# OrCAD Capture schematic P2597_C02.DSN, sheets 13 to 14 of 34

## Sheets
13 21_GPIO Expanders: size Custom
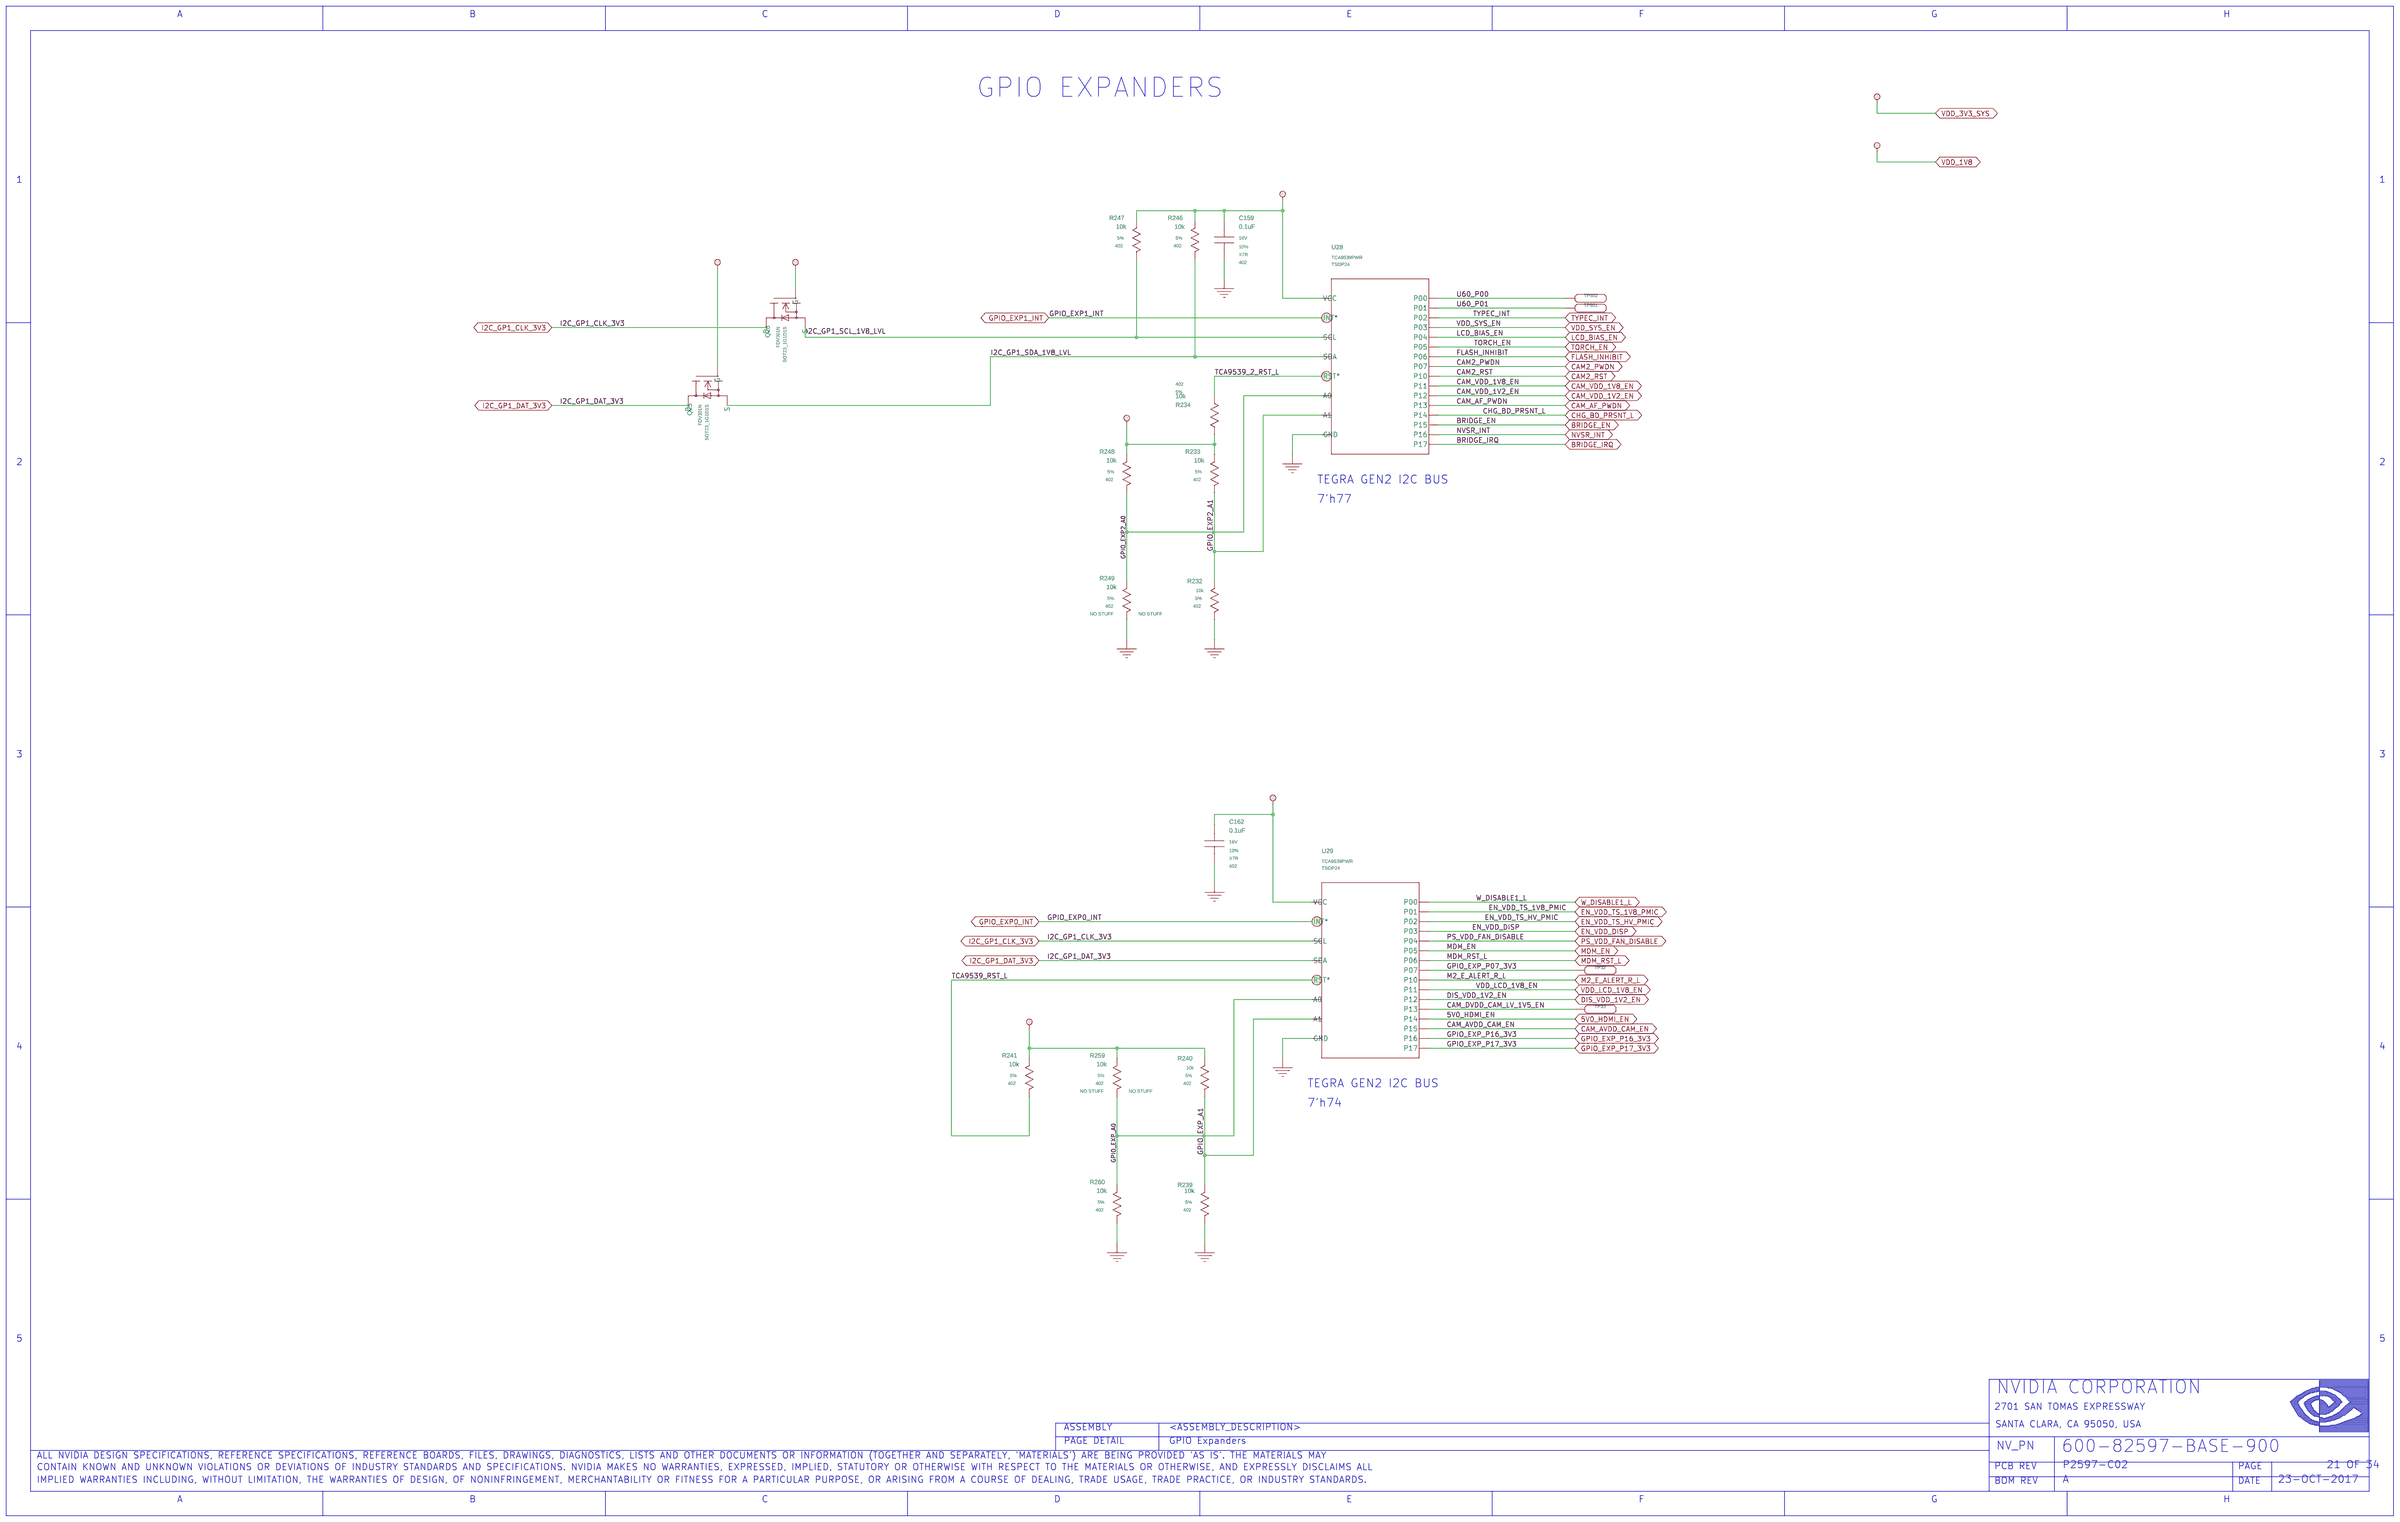
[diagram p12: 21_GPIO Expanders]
14 20_ON OFF CONTROL OUTPUT LOGI: size Custom
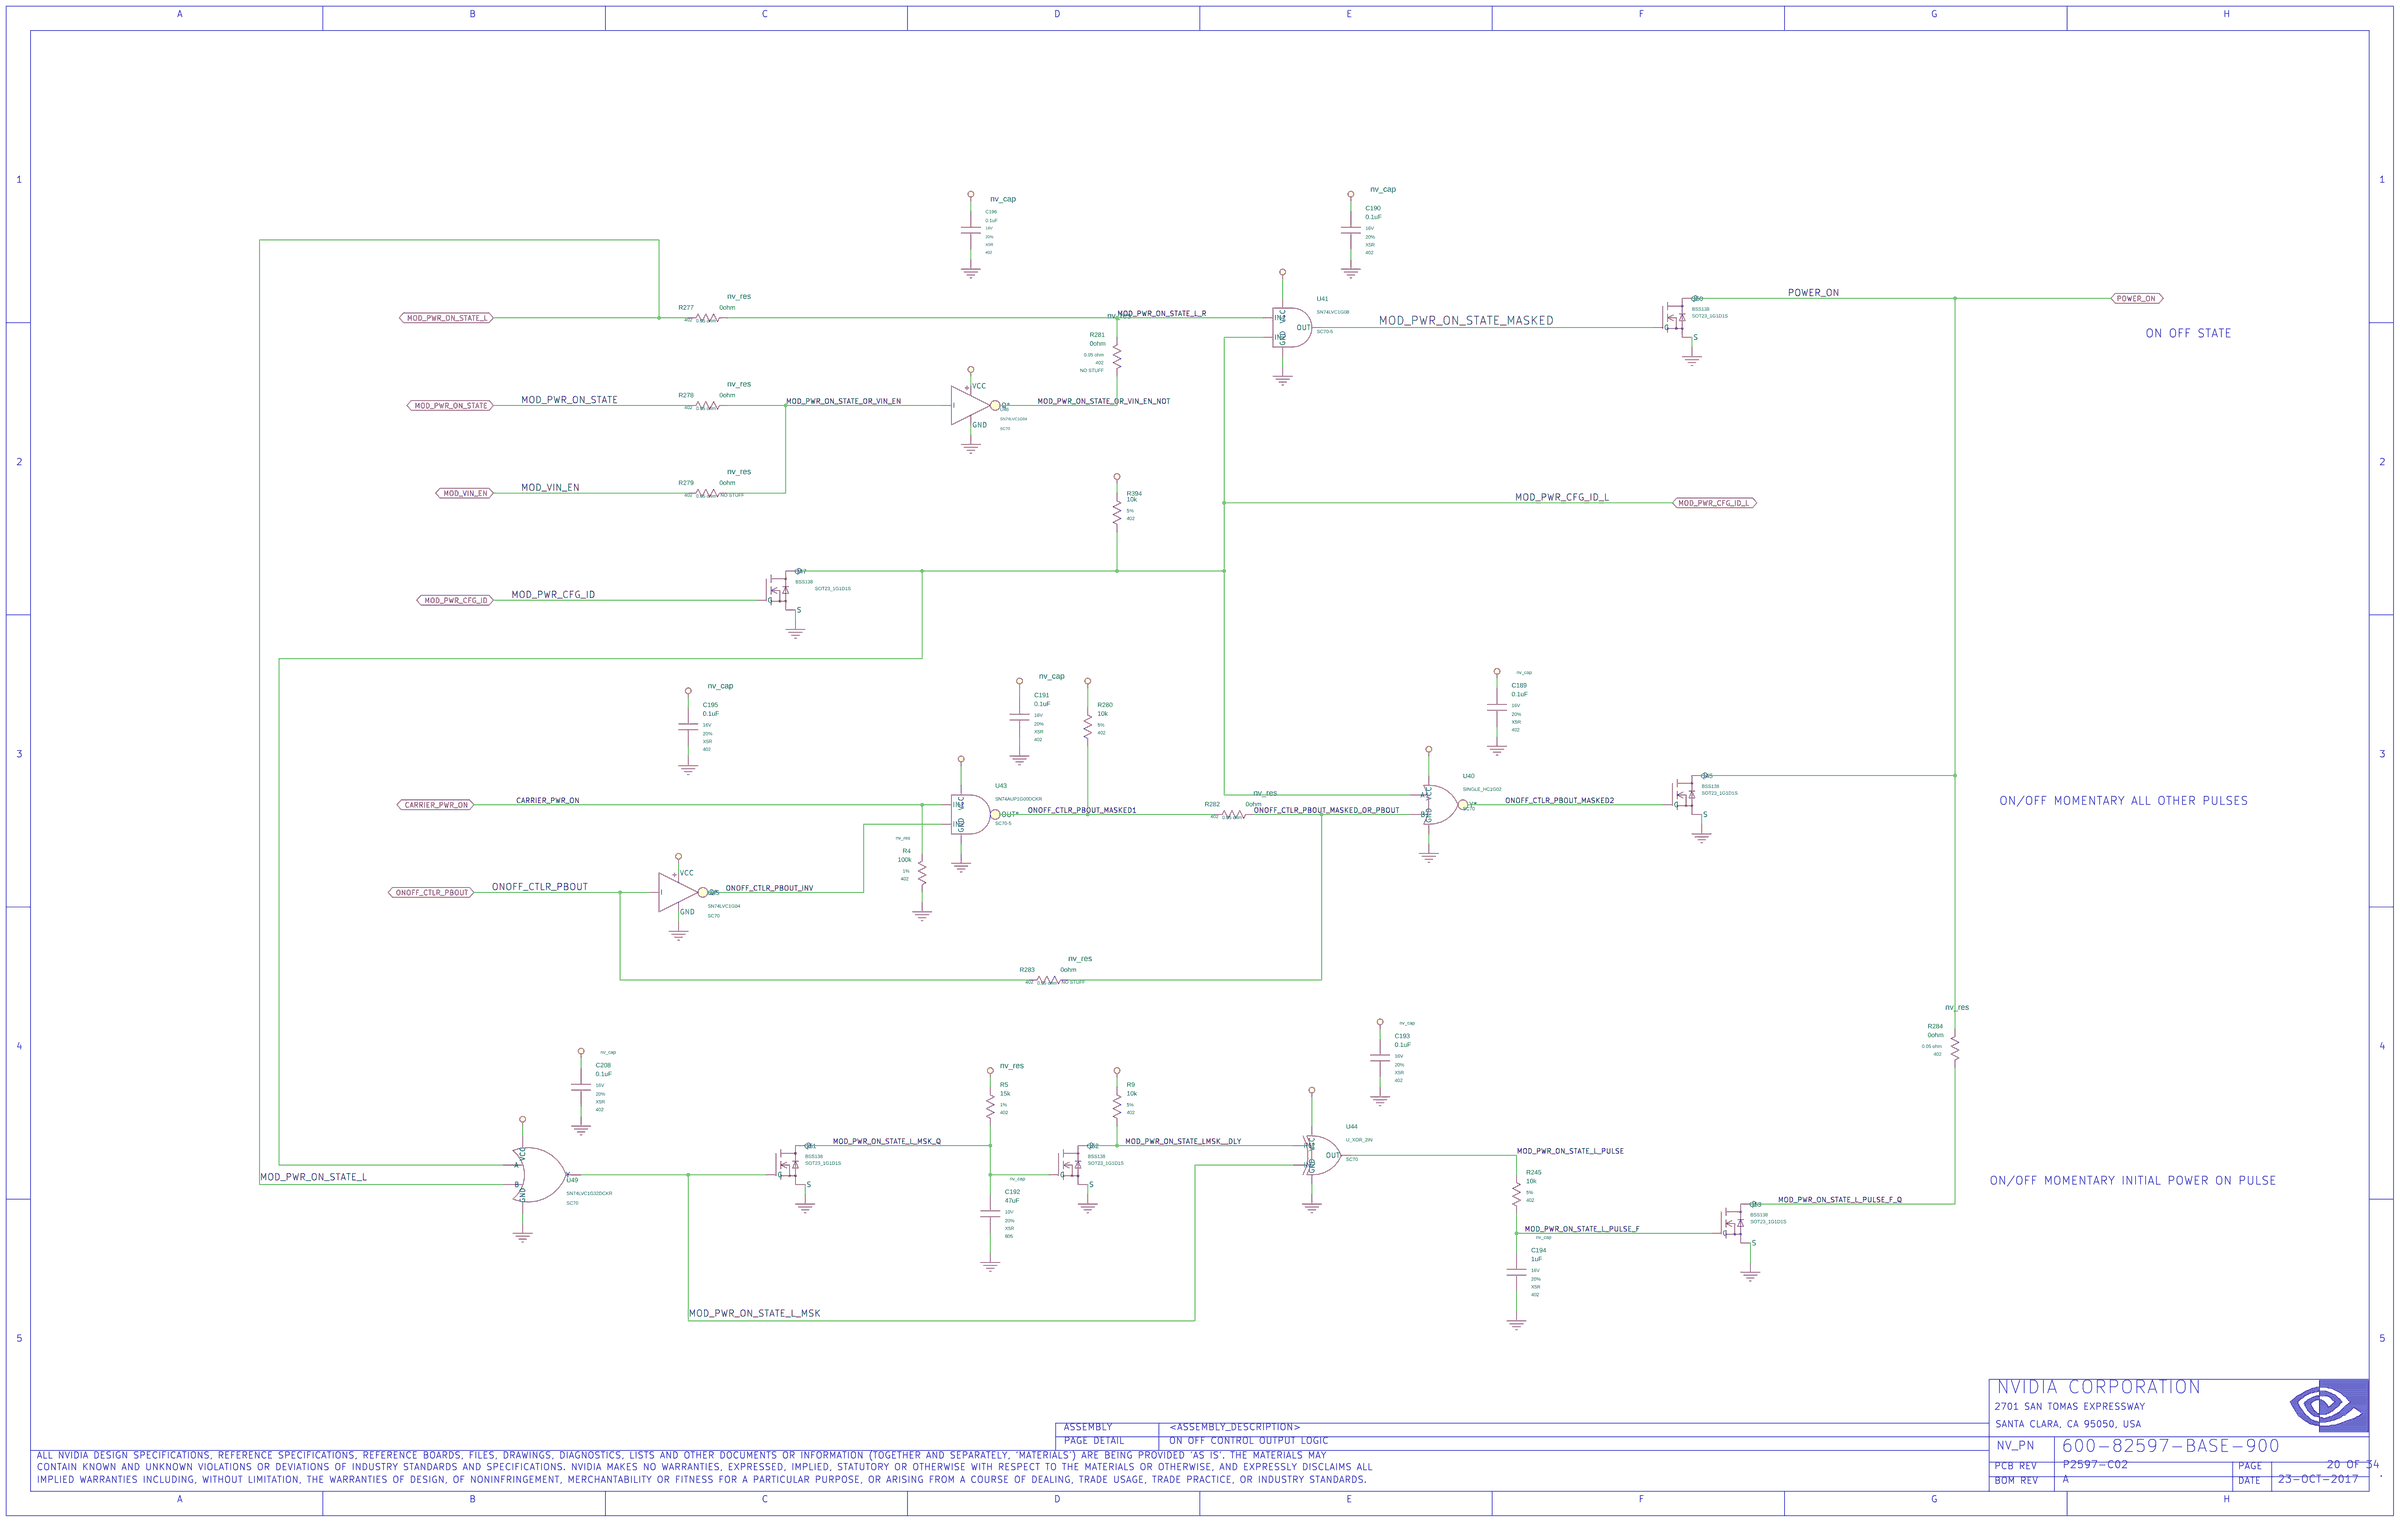
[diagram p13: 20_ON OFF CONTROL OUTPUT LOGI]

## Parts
sheet 20_ON OFF CONTROL OUTPUT LOGI
C189  0.1uF  [402]
C190  0.1uF  [402]
C191  0.1uF  [402]
C192  47uF  [805]
C193  0.1uF  [402]
C194  1uF  [402]
C195  0.1uF  [402]
C196  0.1uF  [402]
C208  0.1uF  [402]
Q45  Q_FET_N_ENH  [SOT23]
Q47  Q_FET_N_ENH  [SOT23]
Q50  Q_FET_N_ENH  [SOT23]
Q51  Q_FET_N_ENH  [SOT23]
Q52  Q_FET_N_ENH  [SOT23]
Q53  Q_FET_N_ENH  [SOT23]
R4  100k  [402]
R5  15k  [402]
R9  10k  [402]
R245  10k  [402]
R277  0ohm  [402]
R278  0ohm  [402]
R279  0ohm  [402]
R280  10k  [402]
R281  0ohm  [402]
R282  0ohm  [402]
R283  0ohm  [402]
R284  0ohm  [402]
R394  10k  [402]
U40  U_NOR_2IN  [SC70_5]
U41  U_AND_2IN  [SC70_5]
U43  U_NAND_2IN  [SC70_5]
U44  U_XOR_2IN  [SC70_5]
U45  U_NOT  [SC70_5]
U46  U_NOT  [SC70_5]
U49  U_OR_2IN  [SC70_5]
sheet 21_GPIO Expanders
C159  0.1uF  [402]
C162  0.1uF  [402]
Q25  Q_FET_N_ENH  [SOT23]
Q26  Q_FET_N_ENH  [SOT23]
R232  10k  [402]
R233  10k  [402]
R234  10k  [402]
R239  10k  [402]
R240  10k  [402]
R241  10k  [402]
R246  10k  [402]
R247  10k  [402]
R248  10k  [402]
R249  10k  [402]
R259  10k  [402]
R260  10k  [402]
TP32  LABTESTPOINT  [LTPT28C49P]
TP33  LABTESTPOINT  [LTPT28C49P]
TP501  LABTESTPOINT  [LTPT28C49P]
TP502  LABTESTPOINT  [LTPT28C49P]
U28  U_I2C_EXP_TCA9539  [XSOP24_P065_079X045]
U29  U_I2C_EXP_TCA9539  [XSOP24_P065_079X045]

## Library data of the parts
C189 = C: ASSEMBLY: ON_OFF_CTRL; CDS_LIB: discrete; CDS_PART_NAME: C_0402-0.1UF,X5R,20%,16V,032-0877-000; CDS_PHYS_PART_NAME: C_0402-0.1UF,X5R,20%,16V,032-0877-000-0.1UF,032-0877-000; CDS_SEC: 1; DEVICE_TYPENAME: C_0402-01UFX5R2016V032-0877-000-01UF032-0877-000; DRAWING: @P2597_C02_LIB.P2597_C02(SCH_1):PAGE20; MAT: X5R; MAX_VOLTAGE: 16V; NV_PN: 032-0877-000; PATH: I11; PHYS_PAGE: 20; ROT: 0; SEC: 1; SIGNAL_MODEL: nv_cap; TOL: 20%; VER: 1; XY: (-4500,4000)
C190 = C: ASSEMBLY: ON_OFF_CTRL; CDS_LIB: discrete; CDS_PART_NAME: C_0402-0.1UF,X5R,20%,16V,032-0877-000; CDS_PHYS_PART_NAME: C_0402-0.1UF,X5R,20%,16V,032-0877-000-0.1UF,032-0877-000; CDS_SEC: 1; DEVICE_TYPENAME: C_0402-01UFX5R2016V032-0877-000-01UF032-0877-000; DRAWING: @P2597_C02_LIB.P2597_C02(SCH_1):PAGE20; MAT: X5R; MAX_VOLTAGE: 16V; NV_PN: 032-0877-000; PATH: I23; PHYS_PAGE: 20; ROT: 0; SEC: 1; SIGNAL_MODEL: nv_cap; TOL: 20%; VER: 1; XY: (-5250,6450)
C191 = C: ASSEMBLY: ON_OFF_CTRL; CDS_LIB: discrete; CDS_PART_NAME: C_0402-0.1UF,X5R,20%,16V,032-0877-000; CDS_PHYS_PART_NAME: C_0402-0.1UF,X5R,20%,16V,032-0877-000-0.1UF,032-0877-000; CDS_SEC: 1; DEVICE_TYPENAME: C_0402-01UFX5R2016V032-0877-000-01UF032-0877-000; DRAWING: @P2597_C02_LIB.P2597_C02(SCH_1):PAGE20; MAT: X5R; MAX_VOLTAGE: 16V; NV_PN: 032-0877-000; PATH: I19; PHYS_PAGE: 20; ROT: 0; SEC: 1; SIGNAL_MODEL: nv_cap; TOL: 20%; VER: 1; XY: (-6950,3950)
C192 = C: ASSEMBLY: ON_OFF_CTRL; CDS_LIB: discrete; CDS_PART_NAME: C_0805-47UF,X5R,20%,10V,032-0775-000; CDS_PHYS_PART_NAME: C_0805-47UF,X5R,20%,10V,032-0775-000-032-0775-000,47UF; CDS_SEC: 1; DEVICE_TYPENAME: C_0805-47UFX5R2010V032-0775-000-032-0775-00047UF; DRAWING: @P2597_C02_LIB.P2597_C02(SCH_1):PAGE20; MAT: X5R; MAX_VOLTAGE: 10V; NV_PN: 032-0775-000; PATH: I42; PHYS_PAGE: 20; ROT: 0; SEC: 1; SIGNAL_MODEL: nv_cap; TOL: 20%; VER: 1; XY: (-7100,1400)
C193 = C: ASSEMBLY: ON_OFF_CTRL; CDS_LIB: discrete; CDS_PART_NAME: C_0402-0.1UF,X5R,20%,16V,032-0877-000; CDS_PHYS_PART_NAME: C_0402-0.1UF,X5R,20%,16V,032-0877-000-0.1UF,032-0877-000; CDS_SEC: 1; DEVICE_TYPENAME: C_0402-01UFX5R2016V032-0877-000-01UF032-0877-000; DRAWING: @P2597_C02_LIB.P2597_C02(SCH_1):PAGE20; MAT: X5R; MAX_VOLTAGE: 16V; NV_PN: 032-0877-000; PATH: I5; PHYS_PAGE: 20; ROT: 0; SEC: 1; SIGNAL_MODEL: nv_cap; TOL: 20%; VER: 1; XY: (-5100,2200)
C194 = C: ASSEMBLY: ON_OFF_CTRL; CDS_LIB: discrete; CDS_PART_NAME: C_0402-1UF,X5R,20%,16V,032-0521-000; CDS_PHYS_PART_NAME: C_0402-1UF,X5R,20%,16V,032-0521-000-032-0521-000,1UF; CDS_SEC: 1; DEVICE_TYPENAME: C_0402-1UFX5R2016V032-0521-000-032-0521-0001UF; DRAWING: @P2597_C02_LIB.P2597_C02(SCH_1):PAGE20; MAT: X5R; MAX_VOLTAGE: 16V; NV_PN: 032-0521-000; PATH: I36; PHYS_PAGE: 20; ROT: 0; SEC: 1; SIGNAL_MODEL: nv_cap; TOL: 20%; VER: 1; XY: (-4400,1100)
C195 = C: ASSEMBLY: ON_OFF_CTRL; CDS_LIB: discrete; CDS_PART_NAME: C_0402-0.1UF,X5R,20%,16V,032-0877-000; CDS_PHYS_PART_NAME: C_0402-0.1UF,X5R,20%,16V,032-0877-000-0.1UF,032-0877-000; CDS_SEC: 1; DEVICE_TYPENAME: C_0402-01UFX5R2016V032-0877-000-01UF032-0877-000; DRAWING: @P2597_C02_LIB.P2597_C02(SCH_1):PAGE20; MAT: X5R; MAX_VOLTAGE: 16V; NV_PN: 032-0877-000; PATH: I55; PHYS_PAGE: 20; ROT: 0; SEC: 1; SIGNAL_MODEL: nv_cap; TOL: 20%; VER: 1; XY: (-8650,3900)
C196 = C: ASSEMBLY: ON_OFF_CTRL; CDS_LIB: discrete; CDS_PART_NAME: C_0402-0.1UF,X5R,20%,16V,032-0877-000; CDS_PHYS_PART_NAME: C_0402-0.1UF,X5R,20%,16V,032-0877-000-0.1UF,032-0877-000; CDS_SEC: 1; DEVICE_TYPENAME: C_0402-01UFX5R2016V032-0877-000-01UF032-0877-000; DRAWING: @P2597_C02_LIB.P2597_C02(SCH_1):PAGE20; MAT: X5R; MAX_VOLTAGE: 16V; NV_PN: 032-0877-000; PATH: I88; PHYS_PAGE: 20; ROT: 0; SEC: 1; SIGNAL_MODEL: nv_cap; TOL: 20%; VER: 1; XY: (-7200,6450)
C208 = C: ASSEMBLY: ON_OFF_CTRL; CDS_LIB: discrete; CDS_PART_NAME: C_0402-0.1UF,X5R,20%,16V,032-0877-000; CDS_PHYS_PART_NAME: C_0402-0.1UF,X5R,20%,16V,032-0877-000-0.1UF,032-0877-000; CDS_SEC: 1; DEVICE_TYPENAME: C_0402-01UFX5R2016V032-0877-000-01UF032-0877-000; DRAWING: @P2597_C02_LIB.P2597_C02(SCH_1):PAGE20; MAT: X5R; MAX_VOLTAGE: 16V; NV_PN: 032-0877-000; PATH: I104; PHYS_PAGE: 20; ROT: 0; SEC: 1; SIGNAL_MODEL: nv_cap; TOL: 20%; VER: 1; XY: (-9200,2050)
Q45 = Q_FET_N_ENH#2: ASSEMBLY: ON_OFF_CTRL; CDS_LIB: discrete; CDS_PART_NAME: Q_FET_N_ENH_SOT23_1G1D1S-BSS138,50V,3500MOHM@10V / 3500MOHM@4.5V / 3500MOHM@2.5V,0.2A,0.2A,20V,0.3W,[ ]@10V / [ ]@4.5V / [ ]@2A; CDS_PHYS_PART_NAME: Q_FET_N_ENH_SOT23_1G1D1S-BSS138,50V,3500MOHM@10V / 3500MOHM@4.5V / 3500MOHM@2.5V,0.2A,0.2A,20V,0.3W,[ ]@10V / [ ]@4.5V / [ ]@2B; CDS_SEC: 1; CONTINUOUS_CURRENT: 0.2A; CaptureCellPackProp: Q_FET_N_ENH__sym_2##2; DEVICE_TYPENAME: Q_FET_N_ENH_SOT23_1G1D1S-BSS13850V3500MOHM10V3500MOHM45V3500MOHM25V02A02A20V03W10V45V2B; DRAWING: @P2597_C02_LIB.P2597_C02(SCH_1):PAGE20; MAX_CURRENT: 0.2A; MAX_VOLTAGE: 50V; MAX_WATTAGE: 0.3W; NV_NAME: BSS138; NV_PN: 300-0156-000; PACK_TYPE: SOT23_1G1D1S; PATH: I9; PHYS_PAGE: 20; Q_G: [ ]@10V / [ ]@4.5V / [ ]@2.5V; ROT: 0; R_DS_ON: 3500mohm@10V / 3500mohm@4.5V / 3500mohm@2.5V; SEC: 1; VER: 2; V_BE_GS: 20V; XY: (-3550,3550)
Q47 = Q_FET_N_ENH#2: ASSEMBLY: ON_OFF_CTRL; CDS_LIB: discrete; CDS_PART_NAME: Q_FET_N_ENH_SOT23_1G1D1S-BSS138,50V,3500MOHM@10V / 3500MOHM@4.5V / 3500MOHM@2.5V,0.2A,0.2A,20V,0.3W,[ ]@10V / [ ]@4.5V / [ ]@2A; CDS_PHYS_PART_NAME: Q_FET_N_ENH_SOT23_1G1D1S-BSS138,50V,3500MOHM@10V / 3500MOHM@4.5V / 3500MOHM@2.5V,0.2A,0.2A,20V,0.3W,[ ]@10V / [ ]@4.5V / [ ]@2B; CDS_SEC: 1; CONTINUOUS_CURRENT: 0.2A; CaptureCellPackProp: Q_FET_N_ENH__sym_2##2; DEVICE_TYPENAME: Q_FET_N_ENH_SOT23_1G1D1S-BSS13850V3500MOHM10V3500MOHM45V3500MOHM25V02A02A20V03W10V45V2B; DRAWING: @P2597_C02_LIB.P2597_C02(SCH_1):PAGE20; MAX_CURRENT: 0.2A; MAX_VOLTAGE: 50V; MAX_WATTAGE: 0.3W; NV_NAME: BSS138; NV_PN: 300-0156-000; PACK_TYPE: SOT23_1G1D1S; PATH: I97; PHYS_PAGE: 20; Q_G: [ ]@10V / [ ]@4.5V / [ ]@2.5V; ROT: 0; R_DS_ON: 3500mohm@10V / 3500mohm@4.5V / 3500mohm@2.5V; SEC: 1; VER: 2; V_BE_GS: 20V; XY: (-8200,4600)
Q50 = Q_FET_N_ENH#2: ASSEMBLY: ON_OFF_CTRL; CDS_LIB: discrete; CDS_PART_NAME: Q_FET_N_ENH_SOT23_1G1D1S-BSS138,50V,3500MOHM@10V / 3500MOHM@4.5V / 3500MOHM@2.5V,0.2A,0.2A,20V,0.3W,[ ]@10V / [ ]@4.5V / [ ]@2A; CDS_PHYS_PART_NAME: Q_FET_N_ENH_SOT23_1G1D1S-BSS138,50V,3500MOHM@10V / 3500MOHM@4.5V / 3500MOHM@2.5V,0.2A,0.2A,20V,0.3W,[ ]@10V / [ ]@4.5V / [ ]@2B; CDS_SEC: 1; CONTINUOUS_CURRENT: 0.2A; CaptureCellPackProp: Q_FET_N_ENH__sym_2##2; DEVICE_TYPENAME: Q_FET_N_ENH_SOT23_1G1D1S-BSS13850V3500MOHM10V3500MOHM45V3500MOHM25V02A02A20V03W10V45V2B; DRAWING: @P2597_C02_LIB.P2597_C02(SCH_1):PAGE20; MAX_CURRENT: 0.2A; MAX_VOLTAGE: 50V; MAX_WATTAGE: 0.3W; NV_NAME: BSS138; NV_PN: 300-0156-000; PACK_TYPE: SOT23_1G1D1S; PATH: I21; PHYS_PAGE: 20; Q_G: [ ]@10V / [ ]@4.5V / [ ]@2.5V; ROT: 0; R_DS_ON: 3500mohm@10V / 3500mohm@4.5V / 3500mohm@2.5V; SEC: 1; VER: 2; V_BE_GS: 20V; XY: (-3600,6000)
Q51 = Q_FET_N_ENH#2: ASSEMBLY: ON_OFF_CTRL; CDS_LIB: discrete; CDS_PART_NAME: Q_FET_N_ENH_SOT23_1G1D1S-BSS138,50V,3500MOHM@10V / 3500MOHM@4.5V / 3500MOHM@2.5V,0.2A,0.2A,20V,0.3W,[ ]@10V / [ ]@4.5V / [ ]@2A; CDS_PHYS_PART_NAME: Q_FET_N_ENH_SOT23_1G1D1S-BSS138,50V,3500MOHM@10V / 3500MOHM@4.5V / 3500MOHM@2.5V,0.2A,0.2A,20V,0.3W,[ ]@10V / [ ]@4.5V / [ ]@2B; CDS_SEC: 1; CONTINUOUS_CURRENT: 0.2A; CaptureCellPackProp: Q_FET_N_ENH__sym_2##2; DEVICE_TYPENAME: Q_FET_N_ENH_SOT23_1G1D1S-BSS13850V3500MOHM10V3500MOHM45V3500MOHM25V02A02A20V03W10V45V2B; DRAWING: @P2597_C02_LIB.P2597_C02(SCH_1):PAGE20; MAX_CURRENT: 0.2A; MAX_VOLTAGE: 50V; MAX_WATTAGE: 0.3W; NV_NAME: BSS138; NV_PN: 300-0156-000; PACK_TYPE: SOT23_1G1D1S; PATH: I46; PHYS_PAGE: 20; Q_G: [ ]@10V / [ ]@4.5V / [ ]@2.5V; ROT: 0; R_DS_ON: 3500mohm@10V / 3500mohm@4.5V / 3500mohm@2.5V; SEC: 1; VER: 2; V_BE_GS: 20V; XY: (-8150,1650)
Q52 = Q_FET_N_ENH#2: ASSEMBLY: ON_OFF_CTRL; CDS_LIB: discrete; CDS_PART_NAME: Q_FET_N_ENH_SOT23_1G1D1S-BSS138,50V,3500MOHM@10V / 3500MOHM@4.5V / 3500MOHM@2.5V,0.2A,0.2A,20V,0.3W,[ ]@10V / [ ]@4.5V / [ ]@2A; CDS_PHYS_PART_NAME: Q_FET_N_ENH_SOT23_1G1D1S-BSS138,50V,3500MOHM@10V / 3500MOHM@4.5V / 3500MOHM@2.5V,0.2A,0.2A,20V,0.3W,[ ]@10V / [ ]@4.5V / [ ]@2B; CDS_SEC: 1; CONTINUOUS_CURRENT: 0.2A; CaptureCellPackProp: Q_FET_N_ENH__sym_2##2; DEVICE_TYPENAME: Q_FET_N_ENH_SOT23_1G1D1S-BSS13850V3500MOHM10V3500MOHM45V3500MOHM25V02A02A20V03W10V45V2B; DRAWING: @P2597_C02_LIB.P2597_C02(SCH_1):PAGE20; MAX_CURRENT: 0.2A; MAX_VOLTAGE: 50V; MAX_WATTAGE: 0.3W; NV_NAME: BSS138; NV_PN: 300-0156-000; PACK_TYPE: SOT23_1G1D1S; PATH: I41; PHYS_PAGE: 20; Q_G: [ ]@10V / [ ]@4.5V / [ ]@2.5V; ROT: 0; R_DS_ON: 3500mohm@10V / 3500mohm@4.5V / 3500mohm@2.5V; SEC: 1; VER: 2; V_BE_GS: 20V; XY: (-6700,1650)
Q53 = Q_FET_N_ENH#2: ASSEMBLY: ON_OFF_CTRL; CDS_LIB: discrete; CDS_PART_NAME: Q_FET_N_ENH_SOT23_1G1D1S-BSS138,50V,3500MOHM@10V / 3500MOHM@4.5V / 3500MOHM@2.5V,0.2A,0.2A,20V,0.3W,[ ]@10V / [ ]@4.5V / [ ]@2A; CDS_PHYS_PART_NAME: Q_FET_N_ENH_SOT23_1G1D1S-BSS138,50V,3500MOHM@10V / 3500MOHM@4.5V / 3500MOHM@2.5V,0.2A,0.2A,20V,0.3W,[ ]@10V / [ ]@4.5V / [ ]@2B; CDS_SEC: 1; CONTINUOUS_CURRENT: 0.2A; CaptureCellPackProp: Q_FET_N_ENH__sym_2##2; DEVICE_TYPENAME: Q_FET_N_ENH_SOT23_1G1D1S-BSS13850V3500MOHM10V3500MOHM45V3500MOHM25V02A02A20V03W10V45V2B; DRAWING: @P2597_C02_LIB.P2597_C02(SCH_1):PAGE20; MAX_CURRENT: 0.2A; MAX_VOLTAGE: 50V; MAX_WATTAGE: 0.3W; NV_NAME: BSS138; NV_PN: 300-0156-000; PACK_TYPE: SOT23_1G1D1S; PATH: I33; PHYS_PAGE: 20; Q_G: [ ]@10V / [ ]@4.5V / [ ]@2.5V; ROT: 0; R_DS_ON: 3500mohm@10V / 3500mohm@4.5V / 3500mohm@2.5V; SEC: 1; VER: 2; V_BE_GS: 20V; XY: (-3300,1350)
R4 = R#1: ASSEMBLY: ON_OFF_CTRL; CDS_LIB: discrete; CDS_PART_NAME: R_0402-100K,1 %,62.5MW,195-0005-000; CDS_PHYS_PART_NAME: R_0402-100K,1 %,62.5MW,195-0005-000-100K,195-0005-000; CDS_SEC: 1; CHIPS_PART_NAME: R; DEVICE_TYPENAME: R_0402-100K1625MW195-0005-000-100K195-0005-000; DRAWING: @P2597_C02_LIB.P2597_C02(SCH_1):PAGE20; MAX_WATTAGE: 62.5mW; NV_PN: 195-0005-000; PATH: I60; PHYS_PAGE: 20; ROT: 2; SEC: 1; SIGNAL_MODEL: nv_res; TOL: 1%; VER: 2; XY: (-7450,3150)
R5 = R#1: ASSEMBLY: ON_OFF_CTRL; CDS_LIB: discrete; CDS_PART_NAME: R_0402-15K,1 %,62.5MW,195-0090-000; CDS_PHYS_PART_NAME: R_0402-15K,1 %,62.5MW,195-0090-000-15K,195-0090-000; CDS_SEC: 1; CHIPS_PART_NAME: R; DEVICE_TYPENAME: R_0402-15K1625MW195-0090-000-15K195-0090-000; DRAWING: @P2597_C02_LIB.P2597_C02(SCH_1):PAGE20; MAX_WATTAGE: 62.5mW; NV_PN: 195-0090-000; PATH: I32; PHYS_PAGE: 20; ROT: 0; SEC: 1; SIGNAL_MODEL: nv_res; TOL: 1%; VER: 2; XY: (-7100,1950)
R9 = R#1: ASSEMBLY: ON_OFF_CTRL; CDS_LIB: discrete; CDS_PART_NAME: R_0402-10K,5 %,62.5MW,195-0486-000; CDS_PHYS_PART_NAME: R_0402-10K,5 %,62.5MW,195-0486-000-10K,195-0486-000; CDS_SEC: 1; CHIPS_PART_NAME: R; DEVICE_TYPENAME: R_0402-10K5625MW195-0486-000-10K195-0486-000; DRAWING: @P2597_C02_LIB.P2597_C02(SCH_1):PAGE20; MAX_WATTAGE: 62.5mW; NV_PN: 195-0486-000; PATH: I29; PHYS_PAGE: 20; ROT: 0; SEC: 1; SIGNAL_MODEL: DEFAULT_RESISTOR_10000OHM_2_1; TOL: 5%; VER: 2; XY: (-6450,1950)
R245 = R#1: ASSEMBLY: ON_OFF_CTRL; CDS_LIB: discrete; CDS_PART_NAME: R_0402-10K,5 %,62.5MW,195-0486-000; CDS_PHYS_PART_NAME: R_0402-10K,5 %,62.5MW,195-0486-000-10K,195-0486-000; CDS_SEC: 1; CHIPS_PART_NAME: R; DEVICE_TYPENAME: R_0402-10K5625MW195-0486-000-10K195-0486-000; DRAWING: @P2597_C02_LIB.P2597_C02(SCH_1):PAGE20; MAX_WATTAGE: 62.5mW; NV_PN: 195-0486-000; PATH: I35; PHYS_PAGE: 20; ROT: 0; SEC: 1; SIGNAL_MODEL: DEFAULT_RESISTOR_10000OHM_2_1; TOL: 5%; VER: 2; XY: (-4400,1500)
R277 = R: ASSEMBLY: ON_OFF_CTRL_STATE_PWRON_INV_BYPASS_CMPLX; CDS_LIB: discrete; CDS_PART_NAME: R_0402-0OHM,0.05 OHM,62.5MW,195-2655-000; CDS_PHYS_PART_NAME: R_0402-0OHM,0.05 OHM,62.5MW,195-2655-000-0OHM,195-2655-000; CDS_SEC: 1; DEVICE_TYPENAME: R_0402-0OHM005OHM625MW195-2655-000-0OHM195-2655-000; DRAWING: @P2597_C02_LIB.P2597_C02(SCH_1):PAGE20; MAX_WATTAGE: 62.5mW; NV_PN: 195-2655-000; PATH: I93; PHYS_PAGE: 20; ROT: 0; SEC: 1; SIGNAL_MODEL: nv_res; TOL: 0.05 ohm; VER: 1; XY: (-8550,6000)
R278 = R: ASSEMBLY: ON_OFF_CTRL_STATE_PWRON2INV_CMPLX; CDS_LIB: discrete; CDS_PART_NAME: R_0402-0OHM,0.05 OHM,62.5MW,195-2655-000; CDS_PHYS_PART_NAME: R_0402-0OHM,0.05 OHM,62.5MW,195-2655-000-0OHM,195-2655-000; CDS_SEC: 1; DEVICE_TYPENAME: R_0402-0OHM005OHM625MW195-2655-000-0OHM195-2655-000; DRAWING: @P2597_C02_LIB.P2597_C02(SCH_1):PAGE20; MAX_WATTAGE: 62.5mW; NV_PN: 195-2655-000; PATH: I92; PHYS_PAGE: 20; ROT: 0; SEC: 1; SIGNAL_MODEL: nv_res; TOL: 0.05 ohm; VER: 1; XY: (-8550,5550)
R279 = R: ASSEMBLY: ON_OFF_CTRL_STATE_VINEN2INV_SMPL; CDS_LIB: discrete; CDS_PART_NAME: R_0402-0OHM,0.05 OHM,62.5MW,195-2655-000; CDS_PHYS_PART_NAME: R_0402-0OHM,0.05 OHM,62.5MW,195-2655-000-0OHM,195-2655-000; CDS_SEC: 1; DEVICE_TYPENAME: R_0402-0OHM005OHM625MW195-2655-000-0OHM195-2655-000; DRAWING: @P2597_C02_LIB.P2597_C02(SCH_1):PAGE20; MAX_WATTAGE: 62.5mW; NV_PN: 195-2655-000; PATH: I91; PHYS_PAGE: 20; ROT: 0; SEC: 1; SIGNAL_MODEL: nv_res; SKU: NO STUFF; TOL: 0.05 ohm; VER: 1; XY: (-8550,5100)
R280 = R#1: ASSEMBLY: ON_OFF_CTRL; CDS_LIB: discrete; CDS_PART_NAME: R_0402-10K,5 %,62.5MW,195-0486-000; CDS_PHYS_PART_NAME: R_0402-10K,5 %,62.5MW,195-0486-000-10K,195-0486-000; CDS_SEC: 1; CHIPS_PART_NAME: R; DEVICE_TYPENAME: R_0402-10K5625MW195-0486-000-10K195-0486-000; DRAWING: @P2597_C02_LIB.P2597_C02(SCH_1):PAGE20; MAX_WATTAGE: 62.5mW; NV_PN: 195-0486-000; PATH: I17; PHYS_PAGE: 20; ROT: 0; SEC: 1; SIGNAL_MODEL: DEFAULT_RESISTOR_10000OHM_2_1; TOL: 5%; VER: 2; XY: (-6600,3900)
R281 = R#1: ASSEMBLY: ON_OFF_CTRL_STATE_PWRON_VIN_INV; CDS_LIB: discrete; CDS_PART_NAME: R_0402-0OHM,0.05 OHM,62.5MW,195-2655-000; CDS_PHYS_PART_NAME: R_0402-0OHM,0.05 OHM,62.5MW,195-2655-000-0OHM,195-2655-000; CDS_SEC: 1; CHIPS_PART_NAME: R; DEVICE_TYPENAME: R_0402-0OHM005OHM625MW195-2655-000-0OHM195-2655-000; DRAWING: @P2597_C02_LIB.P2597_C02(SCH_1):PAGE20; MAX_WATTAGE: 62.5mW; NV_PN: 195-2655-000; PATH: I64; PHYS_PAGE: 20; ROT: 2; SEC: 1; SIGNAL_MODEL: nv_res; SKU: NO STUFF; TOL: 0.05 ohm; VER: 2; XY: (-6450,5800)
R282 = R: ASSEMBLY: ON_OFF_CTRL_MOM_PBOUT_CMPLX; CDS_LIB: discrete; CDS_PART_NAME: R_0402-0OHM,0.05 OHM,62.5MW,195-2655-000; CDS_PHYS_PART_NAME: R_0402-0OHM,0.05 OHM,62.5MW,195-2655-000-0OHM,195-2655-000; CDS_SEC: 1; DEVICE_TYPENAME: R_0402-0OHM005OHM625MW195-2655-000-0OHM195-2655-000; DRAWING: @P2597_C02_LIB.P2597_C02(SCH_1):PAGE20; MAX_WATTAGE: 62.5mW; NV_PN: 195-2655-000; PATH: I15; PHYS_PAGE: 20; ROT: 0; SEC: 1; SIGNAL_MODEL: nv_res; TOL: 0.05 ohm; VER: 1; XY: (-5850,3450)
R283 = R: ASSEMBLY: ON_OFF_CTRL_MOM_PBOUT_SMPL; CDS_LIB: discrete; CDS_PART_NAME: R_0402-0OHM,0.05 OHM,62.5MW,195-2655-000; CDS_PHYS_PART_NAME: R_0402-0OHM,0.05 OHM,62.5MW,195-2655-000-0OHM,195-2655-000; CDS_SEC: 1; DEVICE_TYPENAME: R_0402-0OHM005OHM625MW195-2655-000-0OHM195-2655-000; DRAWING: @P2597_C02_LIB.P2597_C02(SCH_1):PAGE20; MAX_WATTAGE: 62.5mW; NV_PN: 195-2655-000; PATH: I94; PHYS_PAGE: 20; ROT: 0; SEC: 1; SIGNAL_MODEL: nv_res; SKU: NO STUFF; TOL: 0.05 ohm; VER: 1; XY: (-6800,2600)
R284 = R#1: ASSEMBLY: ON_OFF_CTRL_MOM_INIT_PULSE_OUTPUT_CMPLX; CDS_LIB: discrete; CDS_PART_NAME: R_0402-0OHM,0.05 OHM,62.5MW,195-2655-000; CDS_PHYS_PART_NAME: R_0402-0OHM,0.05 OHM,62.5MW,195-2655-000-0OHM,195-2655-000; CDS_SEC: 1; CHIPS_PART_NAME: R; DEVICE_TYPENAME: R_0402-0OHM005OHM625MW195-2655-000-0OHM195-2655-000; DRAWING: @P2597_C02_LIB.P2597_C02(SCH_1):PAGE20; MAX_WATTAGE: 62.5mW; NV_PN: 195-2655-000; PATH: I2; PHYS_PAGE: 20; ROT: 2; SEC: 1; SIGNAL_MODEL: nv_res; TOL: 0.05 ohm; VER: 2; XY: (-2150,2250)
R394 = R#1: ASSEMBLY: ON_OFF_CTRL; CDS_LIB: discrete; CDS_PART_NAME: R_0402-10K,5 %,62.5MW,195-0486-000; CDS_PHYS_PART_NAME: R_0402-10K,5 %,62.5MW,195-0486-000-10K,195-0486-000; CDS_SEC: 1; CHIPS_PART_NAME: R; DEVICE_TYPENAME: R_0402-10K5625MW195-0486-000-10K195-0486-000; DRAWING: @P2597_C02_LIB.P2597_C02(SCH_1):PAGE20; MAX_WATTAGE: 62.5mW; NV_PN: 195-0486-000; PATH: I96; PHYS_PAGE: 20; ROT: 0; SEC: 1; SIGNAL_MODEL: DEFAULT_RESISTOR_10000OHM_2_1; TOL: 5%; VER: 2; XY: (-6450,5000)
U40 = U_NOR_2IN: ASSEMBLY: ON_OFF_CTRL; CDS_LIB: logic; CDS_PART_NAME: U_NOR_2IN_SC70-SINGLE_HC1G02,GATES - NOR - 2 INPUT,115-0919-000; CDS_PHYS_PART_NAME: U_NOR_2IN_SC70-SINGLE_HC1G02,GATES - NOR - 2 INPUT,115-0919-000-115-0919-000; CDS_SEC: 1; DEVICE_TYPENAME: U_NOR_2IN_SC70-SINGLE_HC1G02GATES-NOR-2INPUT115-0919-000-115-0919-000; DRAWING: @P2597_C02_LIB.P2597_C02(SCH_1):PAGE20; FUNCTION: Gates - NOR - 2 input; NV_NAME: SINGLE_HC1G02; NV_PN: 115-0919-000; PACK_TYPE: SC70; PATH: I14; PHYS_PAGE: 20; ROT: 0; SEC: 1; VER: 1; XY: (-4800,3500)
U41 = U_AND_2IN: ASSEMBLY: ON_OFF_CTRL; CDS_LIB: logic; CDS_PART_NAME: U_AND_2IN_SC70-5-SN74LVC1G08,GATES - AND - 2 INPUT,115-0014-000; CDS_PHYS_PART_NAME: U_AND_2IN_SC70-5-SN74LVC1G08,GATES - AND - 2 INPUT,115-0014-000-115-0014-000; CDS_SEC: 1; DEVICE_TYPENAME: U_AND_2IN_SC70-5-SN74LVC1G08GATES-AND-2INPUT115-0014-000-115-0014-000; DRAWING: @P2597_C02_LIB.P2597_C02(SCH_1):PAGE20; FUNCTION: Gates - AND - 2 input; NV_NAME: SN74LVC1G08; NV_PN: 115-0014-000; PACK_TYPE: SC70-5; PATH: I30; PHYS_PAGE: 20; ROT: 0; SEC: 1; VER: 1; XY: (-5550,5950)
U43 = U_NAND_2IN: ASSEMBLY: ON_OFF_CTRL; CDS_LIB: logic; CDS_PART_NAME: U_NAND_2IN_SC70-5-SN74AUP1G00DCKR,GATES - NAND - 2 INPUT,115-2151-000; CDS_PHYS_PART_NAME: U_NAND_2IN_SC70-5-SN74AUP1G00DCKR,GATES - NAND - 2 INPUT,115-2151-000-115-2151-000; CDS_SEC: 1; DEVICE_TYPENAME: U_NAND_2IN_SC70-5-SN74AUP1G00DCKRGATES-NAND-2INPUT115-2151-000-115-2151-000; DRAWING: @P2597_C02_LIB.P2597_C02(SCH_1):PAGE20; FUNCTION: Gates - NAND - 2 input; NV_NAME: SN74AUP1G00DCKR; NV_PN: 115-2151-000; PACK_TYPE: SC70-5; PATH: I53; PHYS_PAGE: 20; ROT: 0; SEC: 1; VER: 1; XY: (-7200,3450)
U44 = U_XOR_2IN: ASSEMBLY: ON_OFF_CTRL; CDS_LIB: logic; CDS_PART_NAME: U_XOR_2IN_SC70-U_XOR_2IN,GATES - XOR - 2 INPUT,115-0406-000; CDS_PHYS_PART_NAME: U_XOR_2IN_SC70-U_XOR_2IN,GATES - XOR - 2 INPUT,115-0406-000-115-0406-000; CDS_SEC: 1; DEVICE_TYPENAME: U_XOR_2IN_SC70-U_XOR_2INGATES-XOR-2INPUT115-0406-000-115-0406-000; DRAWING: @P2597_C02_LIB.P2597_C02(SCH_1):PAGE20; FUNCTION: Gates - XOR - 2 input; NV_PN: 115-0406-000; PACK_TYPE: SC70; PATH: I38; PHYS_PAGE: 20; ROT: 0; SEC: 1; VER: 1; XY: (-5400,1700)
U45 = U_NOT: ASSEMBLY: ON_OFF_CTRL; CDS_LIB: logic; CDS_PART_NAME: U_NOT_SC70-SN74LVC1G04,GATES - NOT,115-0085-000; CDS_PHYS_PART_NAME: U_NOT_SC70-SN74LVC1G04,GATES - NOT,115-0085-000-115-0085-000; CDS_SEC: 1; DEVICE_TYPENAME: U_NOT_SC70-SN74LVC1G04GATES-NOT115-0085-000-115-0085-000; DRAWING: @P2597_C02_LIB.P2597_C02(SCH_1):PAGE20; FUNCTION: Gates - NOT; NV_NAME: SN74LVC1G04; NV_PN: 115-0085-000; PACK_TYPE: SC70; PATH: I66; PHYS_PAGE: 20; ROT: 0; SEC: 1; VER: 1; XY: (-8700,3050)
U46 = U_NOT: ASSEMBLY: ON_OFF_CTRL; CDS_LIB: logic; CDS_PART_NAME: U_NOT_SC70-SN74LVC1G04,GATES - NOT,115-0085-000; CDS_PHYS_PART_NAME: U_NOT_SC70-SN74LVC1G04,GATES - NOT,115-0085-000-115-0085-000; CDS_SEC: 1; DEVICE_TYPENAME: U_NOT_SC70-SN74LVC1G04GATES-NOT115-0085-000-115-0085-000; DRAWING: @P2597_C02_LIB.P2597_C02(SCH_1):PAGE20; FUNCTION: Gates - NOT; NV_NAME: SN74LVC1G04; NV_PN: 115-0085-000; PACK_TYPE: SC70; PATH: I83; PHYS_PAGE: 20; ROT: 0; SEC: 1; VER: 1; XY: (-7200,5550)
U49 = U_OR_2IN: ASSEMBLY: ON_OFF_CTRL; CDS_LIB: logic; CDS_PART_NAME: U_OR_2IN_SC70-SN74LVC1G32DCKR,GATES - OR - 2 INPUT,115-1426-000; CDS_PHYS_PART_NAME: U_OR_2IN_SC70-SN74LVC1G32DCKR,GATES - OR - 2 INPUT,115-1426-000-115-1426-000; CDS_SEC: 1; DEVICE_TYPENAME: U_OR_2IN_SC70-SN74LVC1G32DCKRGATES-OR-2INPUT115-1426-000-115-1426-000; DRAWING: @P2597_C02_LIB.P2597_C02(SCH_1):PAGE20; FUNCTION: Gates - OR - 2 input; NV_NAME: SN74LVC1G32DCKR; NV_PN: 115-1426-000; PACK_TYPE: SC70; PATH: I100; PHYS_PAGE: 20; ROT: 0; SEC: 1; VER: 1; XY: (-9400,1600)
C159 = C: ASSEMBLY: GPIO; CDS_LIB: discrete; CDS_PART_NAME: C_0402-0.1UF,X7R,10%,16V,036-0014-000; CDS_PHYS_PART_NAME: C_0402-0.1UF,X7R,10%,16V,036-0014-000-0.1UF,036-0014-000; CDS_SEC: 1; DEVICE_TYPENAME: C_0402-01UFX7R1016V036-0014-000-01UF036-0014-000; DRAWING: @P2597_C02_LIB.P2597_C02(SCH_1):PAGE21; MAT: X7R; MAX_VOLTAGE: 16V; NV_PN: 036-0014-000; PATH: I274; PHYS_PAGE: 21; ROT: 0; SEC: 1; SIGNAL_MODEL: nv_cap; TOL: 10%; VER: 1; XY: (-5900,6400)
C162 = C: ASSEMBLY: GPIO; CDS_LIB: discrete; CDS_PART_NAME: C_0402-0.1UF,X7R,10%,16V,036-0014-000; CDS_PHYS_PART_NAME: C_0402-0.1UF,X7R,10%,16V,036-0014-000-0.1UF,036-0014-000; CDS_SEC: 1; DEVICE_TYPENAME: C_0402-01UFX7R1016V036-0014-000-01UF036-0014-000; DRAWING: @P2597_C02_LIB.P2597_C02(SCH_1):PAGE21; MAT: X7R; MAX_VOLTAGE: 16V; NV_PN: 036-0014-000; PATH: I53; PHYS_PAGE: 21; ROT: 0; SEC: 1; SIGNAL_MODEL: nv_cap; TOL: 10%; VER: 1; XY: (-5950,3300)
Q25 = Q_FET_N_ENH#2: ASSEMBLY: GPIO; CDS_LIB: discrete; CDS_PART_NAME: Q_FET_N_ENH_SOT23_1G1D1S-FDV301N,25V,-1000MOHM@10V / 4000MOHM@4.5V / -1000MOHM@2.5V,0.22A,0.5A,8V,0.35W,[ ]@10V / [ ]@4.5V / [A; CDS_PHYS_PART_NAME: Q_FET_N_ENH_SOT23_1G1D1S-FDV301N,25V,-1000MOHM@10V / 4000MOHM@4.5V / -1000MOHM@2.5V,0.22A,0.5A,8V,0.35W,[ ]@10V / [ ]@4.5V / [B; CDS_SEC: 1; CONTINUOUS_CURRENT: 0.22A; CaptureCellPackProp: Q_FET_N_ENH__sym_2##2; DEVICE_TYPENAME: Q_FET_N_ENH_SOT23_1G1D1S-FDV301N25V-1000MOHM10V4000MOHM45V-1000MOHM25V022A05A8V035W10V45VB; DRAWING: @P2597_C02_LIB.P2597_C02(SCH_1):PAGE21; MAX_CURRENT: 0.5A; MAX_VOLTAGE: 25V; MAX_WATTAGE: 0.35W; NV_NAME: FDV301N; NV_PN: 300-0494-000; PACK_TYPE: SOT23_1G1D1S; PATH: I282; PHYS_PAGE: 21; Q_G: [ ]@10V / [ ]@4.5V / [ ]@2.5V; ROT: 3; R_DS_ON: -1000mohm@10V / 4000mohm@4.5V / -1000mohm@2.5V; SEC: 1; SEC_TYPE: SOT23_1G1D1S; VER: 2; V_BE_GS: 8V; XY: (-8550,5650)
Q26 = Q_FET_N_ENH#2: ASSEMBLY: GPIO; CDS_LIB: discrete; CDS_PART_NAME: Q_FET_N_ENH_SOT23_1G1D1S-FDV301N,25V,-1000MOHM@10V / 4000MOHM@4.5V / -1000MOHM@2.5V,0.22A,0.5A,8V,0.35W,[ ]@10V / [ ]@4.5V / [A; CDS_PHYS_PART_NAME: Q_FET_N_ENH_SOT23_1G1D1S-FDV301N,25V,-1000MOHM@10V / 4000MOHM@4.5V / -1000MOHM@2.5V,0.22A,0.5A,8V,0.35W,[ ]@10V / [ ]@4.5V / [B; CDS_SEC: 1; CONTINUOUS_CURRENT: 0.22A; CaptureCellPackProp: Q_FET_N_ENH__sym_2##2; DEVICE_TYPENAME: Q_FET_N_ENH_SOT23_1G1D1S-FDV301N25V-1000MOHM10V4000MOHM45V-1000MOHM25V022A05A8V035W10V45VB; DRAWING: @P2597_C02_LIB.P2597_C02(SCH_1):PAGE21; MAX_CURRENT: 0.5A; MAX_VOLTAGE: 25V; MAX_WATTAGE: 0.35W; NV_NAME: FDV301N; NV_PN: 300-0494-000; PACK_TYPE: SOT23_1G1D1S; PATH: I283; PHYS_PAGE: 21; Q_G: [ ]@10V / [ ]@4.5V / [ ]@2.5V; ROT: 3; R_DS_ON: -1000mohm@10V / 4000mohm@4.5V / -1000mohm@2.5V; SEC: 1; SEC_TYPE: SOT23_1G1D1S; VER: 2; V_BE_GS: 8V; XY: (-8150,6050)
R232 = R#1: ASSEMBLY: GPIO; CDS_LIB: discrete; CDS_PART_NAME: R_0402-10K,5 %,62.5MW,195-0486-000; CDS_PHYS_PART_NAME: R_0402-10K,5 %,62.5MW,195-0486-000-10K,195-0486-000; CDS_SEC: 1; CHIPS_PART_NAME: R; DEVICE_TYPENAME: R_0402-10K5625MW195-0486-000-10K195-0486-000; DRAWING: @P2597_C02_LIB.P2597_C02(SCH_1):PAGE21; MAX_WATTAGE: 62.5mW; NV_PN: 195-0486-000; PATH: I247; PHYS_PAGE: 21; ROT: 2; SEC: 1; SIGNAL_MODEL: nv_res; SKU: NO STUFF; TOL: 5%; VER: 2; XY: (-5950,4550)
R233 = R#1: ASSEMBLY: GPIO; CDS_LIB: discrete; CDS_PART_NAME: R_0402-10K,5 %,62.5MW,195-0486-000; CDS_PHYS_PART_NAME: R_0402-10K,5 %,62.5MW,195-0486-000-10K,195-0486-000; CDS_SEC: 1; CHIPS_PART_NAME: R; DEVICE_TYPENAME: R_0402-10K5625MW195-0486-000-10K195-0486-000; DRAWING: @P2597_C02_LIB.P2597_C02(SCH_1):PAGE21; MAX_WATTAGE: 62.5mW; NV_PN: 195-0486-000; PATH: I253; PHYS_PAGE: 21; ROT: 2; SEC: 1; SIGNAL_MODEL: nv_res; TOL: 5%; VER: 2; XY: (-5950,5200)
R234 = R#1: ASSEMBLY: GPIO; CDS_LIB: discrete; CDS_PART_NAME: R_0402-10K,5 %,62.5MW,195-0486-000; CDS_PHYS_PART_NAME: R_0402-10K,5 %,62.5MW,195-0486-000-10K,195-0486-000; CDS_SEC: 1; CHIPS_PART_NAME: R; DEVICE_TYPENAME: R_0402-10K5625MW195-0486-000-10K195-0486-000; DRAWING: @P2597_C02_LIB.P2597_C02(SCH_1):PAGE21; MAX_WATTAGE: 62.5mW; NV_PN: 195-0486-000; PATH: I256; PHYS_PAGE: 21; ROT: 4; SEC: 1; SIGNAL_MODEL: nv_res; TOL: 5%; VER: 2; XY: (-5950,5500)
R239 = R#1: ASSEMBLY: GPIO; CDS_LIB: discrete; CDS_PART_NAME: R_0402-10K,5 %,62.5MW,195-0486-000; CDS_PHYS_PART_NAME: R_0402-10K,5 %,62.5MW,195-0486-000-10K,195-0486-000; CDS_SEC: 1; CHIPS_PART_NAME: R; DEVICE_TYPENAME: R_0402-10K5625MW195-0486-000-10K195-0486-000; DRAWING: @P2597_C02_LIB.P2597_C02(SCH_1):PAGE21; MAX_WATTAGE: 62.5mW; NV_PN: 195-0486-000; PATH: I30; PHYS_PAGE: 21; ROT: 2; SEC: 1; SIGNAL_MODEL: nv_res; TOL: 5%; VER: 2; XY: (-6000,1450)
R240 = R#1: ASSEMBLY: GPIO; CDS_LIB: discrete; CDS_PART_NAME: R_0402-10K,5 %,62.5MW,195-0486-000; CDS_PHYS_PART_NAME: R_0402-10K,5 %,62.5MW,195-0486-000-10K,195-0486-000; CDS_SEC: 1; CHIPS_PART_NAME: R; DEVICE_TYPENAME: R_0402-10K5625MW195-0486-000-10K195-0486-000; DRAWING: @P2597_C02_LIB.P2597_C02(SCH_1):PAGE21; MAX_WATTAGE: 62.5mW; NV_PN: 195-0486-000; PATH: I32; PHYS_PAGE: 21; ROT: 2; SEC: 1; SIGNAL_MODEL: nv_res; SKU: NO STUFF; TOL: 5%; VER: 2; XY: (-6000,2100)
R241 = R#1: ASSEMBLY: GPIO; CDS_LIB: discrete; CDS_PART_NAME: R_0402-10K,5 %,62.5MW,195-0486-000; CDS_PHYS_PART_NAME: R_0402-10K,5 %,62.5MW,195-0486-000-10K,195-0486-000; CDS_SEC: 1; CHIPS_PART_NAME: R; DEVICE_TYPENAME: R_0402-10K5625MW195-0486-000-10K195-0486-000; DRAWING: @P2597_C02_LIB.P2597_C02(SCH_1):PAGE21; MAX_WATTAGE: 62.5mW; NV_PN: 195-0486-000; PATH: I208; PHYS_PAGE: 21; ROT: 2; SEC: 1; SIGNAL_MODEL: nv_res; TOL: 5%; VER: 2; XY: (-6900,2100)
R246 = R#1: ASSEMBLY: GPIO; CDS_LIB: discrete; CDS_PART_NAME: R_0402-10K,5 %,62.5MW,195-0486-000; CDS_PHYS_PART_NAME: R_0402-10K,5 %,62.5MW,195-0486-000-10K,195-0486-000; CDS_SEC: 1; CHIPS_PART_NAME: R; DEVICE_TYPENAME: R_0402-10K5625MW195-0486-000-10K195-0486-000; DRAWING: @P2597_C02_LIB.P2597_C02(SCH_1):PAGE21; MAX_WATTAGE: 62.5mW; NV_PN: 195-0486-000; PATH: I286; PHYS_PAGE: 21; ROT: 2; SEC: 1; SIGNAL_MODEL: nv_res; TOL: 5%; VER: 2; XY: (-6050,6400)
R247 = R#1: ASSEMBLY: GPIO; CDS_LIB: discrete; CDS_PART_NAME: R_0402-10K,5 %,62.5MW,195-0486-000; CDS_PHYS_PART_NAME: R_0402-10K,5 %,62.5MW,195-0486-000-10K,195-0486-000; CDS_SEC: 1; CHIPS_PART_NAME: R; DEVICE_TYPENAME: R_0402-10K5625MW195-0486-000-10K195-0486-000; DRAWING: @P2597_C02_LIB.P2597_C02(SCH_1):PAGE21; MAX_WATTAGE: 62.5mW; NV_PN: 195-0486-000; PATH: I287; PHYS_PAGE: 21; ROT: 2; SEC: 1; SIGNAL_MODEL: nv_res; TOL: 5%; VER: 2; XY: (-6350,6400)
R248 = R#1: ASSEMBLY: GPIO; CDS_LIB: discrete; CDS_PART_NAME: R_0402-10K,5 %,62.5MW,195-0486-000; CDS_PHYS_PART_NAME: R_0402-10K,5 %,62.5MW,195-0486-000-10K,195-0486-000; CDS_SEC: 1; CHIPS_PART_NAME: R; DEVICE_TYPENAME: R_0402-10K5625MW195-0486-000-10K195-0486-000; DRAWING: @P2597_C02_LIB.P2597_C02(SCH_1):PAGE21; MAX_WATTAGE: 62.5mW; NV_PN: 195-0486-000; PATH: I254; PHYS_PAGE: 21; ROT: 2; SEC: 1; SIGNAL_MODEL: nv_res; TOL: 5%; VER: 2; XY: (-6400,5200)
R249 = R#1: ASSEMBLY: GPIO; CDS_LIB: discrete; CDS_PART_NAME: R_0402-10K,5 %,62.5MW,195-0486-000; CDS_PHYS_PART_NAME: R_0402-10K,5 %,62.5MW,195-0486-000-10K,195-0486-000; CDS_SEC: 1; CHIPS_PART_NAME: R; DEVICE_TYPENAME: R_0402-10K5625MW195-0486-000-10K195-0486-000; DRAWING: @P2597_C02_LIB.P2597_C02(SCH_1):PAGE21; MAX_WATTAGE: 62.5mW; NV_PN: 195-0486-000; PATH: I248; PHYS_PAGE: 21; ROT: 2; SEC: 1; SIGNAL_MODEL: nv_res; SKU: NO STUFF; TOL: 5%; VER: 2; XY: (-6400,4550)
R259 = R#1: ASSEMBLY: GPIO; CDS_LIB: discrete; CDS_PART_NAME: R_0402-10K,5 %,62.5MW,195-0486-000; CDS_PHYS_PART_NAME: R_0402-10K,5 %,62.5MW,195-0486-000-10K,195-0486-000; CDS_SEC: 1; CHIPS_PART_NAME: R; DEVICE_TYPENAME: R_0402-10K5625MW195-0486-000-10K195-0486-000; DRAWING: @P2597_C02_LIB.P2597_C02(SCH_1):PAGE21; MAX_WATTAGE: 62.5mW; NV_PN: 195-0486-000; PATH: I31; PHYS_PAGE: 21; ROT: 2; SEC: 1; SIGNAL_MODEL: nv_res; SKU: NO STUFF; TOL: 5%; VER: 2; XY: (-6450,2100)
R260 = R#1: ASSEMBLY: GPIO; CDS_LIB: discrete; CDS_PART_NAME: R_0402-10K,5 %,62.5MW,195-0486-000; CDS_PHYS_PART_NAME: R_0402-10K,5 %,62.5MW,195-0486-000-10K,195-0486-000; CDS_SEC: 1; CHIPS_PART_NAME: R; DEVICE_TYPENAME: R_0402-10K5625MW195-0486-000-10K195-0486-000; DRAWING: @P2597_C02_LIB.P2597_C02(SCH_1):PAGE21; MAX_WATTAGE: 62.5mW; NV_PN: 195-0486-000; PATH: I26; PHYS_PAGE: 21; ROT: 2; SEC: 1; SIGNAL_MODEL: nv_res; TOL: 5%; VER: 2; XY: (-6450,1450)
TP32 = LABTESTPOINT: CDS_LIB: electro_mechanic; CDS_PART_NAME: LABTESTPOINT_B28-LABTESTPOINT; CDS_PHYS_PART_NAME: LABTESTPOINT_B28-LABTESTPOINT; CDS_SEC: 1; DEVICE_TYPENAME: LABTESTPOINT_B28-LABTESTPOINT; DRAWING: @P2597_C02_LIB.P2597_C02(SCH_1):PAGE21; PACK_TYPE: B28; PATH: I293; PHYS_PAGE: 21; ROT: 0; SEC: 1; VER: 3; XY: (-4050,2650)
TP33 = LABTESTPOINT: CDS_LIB: electro_mechanic; CDS_PART_NAME: LABTESTPOINT_B28-LABTESTPOINT; CDS_PHYS_PART_NAME: LABTESTPOINT_B28-LABTESTPOINT; CDS_SEC: 1; DEVICE_TYPENAME: LABTESTPOINT_B28-LABTESTPOINT; DRAWING: @P2597_C02_LIB.P2597_C02(SCH_1):PAGE21; PACK_TYPE: B28; PATH: I290; PHYS_PAGE: 21; ROT: 0; SEC: 1; VER: 3; XY: (-4050,2450)
TP501 = LABTESTPOINT: CDS_LIB: electro_mechanic; CDS_PART_NAME: LABTESTPOINT_B28-LABTESTPOINT; CDS_PHYS_PART_NAME: LABTESTPOINT_B28-LABTESTPOINT; CDS_SEC: 1; DEVICE_TYPENAME: LABTESTPOINT_B28-LABTESTPOINT; DRAWING: @P2597_C02_LIB.P2597_C02(SCH_1):PAGE21; PACK_TYPE: B28; PATH: I292; PHYS_PAGE: 21; ROT: 0; SEC: 1; VER: 3; XY: (-4100,6050)
TP502 = LABTESTPOINT: CDS_LIB: electro_mechanic; CDS_PART_NAME: LABTESTPOINT_B28-LABTESTPOINT; CDS_PHYS_PART_NAME: LABTESTPOINT_B28-LABTESTPOINT; CDS_SEC: 1; DEVICE_TYPENAME: LABTESTPOINT_B28-LABTESTPOINT; DRAWING: @P2597_C02_LIB.P2597_C02(SCH_1):PAGE21; PACK_TYPE: B28; PATH: I291; PHYS_PAGE: 21; ROT: 0; SEC: 1; VER: 3; XY: (-4100,6100)
U28 = U_I2C_EXP_TCA9539: ASSEMBLY: GPIO; CDS_LIB: digital; CDS_PART_NAME: U_I2C_EXP_TCA9539_TSOP24-TCA9539PWR,I/O EXPANDER,115-0674-000; CDS_PHYS_PART_NAME: U_I2C_EXP_TCA9539_TSOP24-TCA9539PWR,I/O EXPANDER,115-0674-000-115-0674-000; CDS_SEC: 1; DEVICE_TYPENAME: U_I2C_EXP_TCA9539_TSOP24-TCA9539PWRIOEXPANDER115-0674-000-115-0674-000; DRAWING: @P2597_C02_LIB.P2597_C02(SCH_1):PAGE21; INTERFACE: I/O Expander; NV_NAME: TCA9539PWR; NV_PN: 115-0674-000; PACK_TYPE: TSOP24; PATH: I276; PHYS_PAGE: 21; ROT: 0; SEC: 1; SEC_TYPE: TSOP24; VER: 1; XY: (-5100,5750)
U29 = U_I2C_EXP_TCA9539: ASSEMBLY: GPIO; CDS_LIB: digital; CDS_PART_NAME: U_I2C_EXP_TCA9539_TSOP24-TCA9539PWR,I/O EXPANDER,115-0674-000; CDS_PHYS_PART_NAME: U_I2C_EXP_TCA9539_TSOP24-TCA9539PWR,I/O EXPANDER,115-0674-000-115-0674-000; CDS_SEC: 1; DEVICE_TYPENAME: U_I2C_EXP_TCA9539_TSOP24-TCA9539PWRIOEXPANDER115-0674-000-115-0674-000; DRAWING: @P2597_C02_LIB.P2597_C02(SCH_1):PAGE21; INTERFACE: I/O Expander; NV_NAME: TCA9539PWR; NV_PN: 115-0674-000; PACK_TYPE: TSOP24; PATH: I2; PHYS_PAGE: 21; ROT: 0; SEC: 1; SEC_TYPE: TSOP24; VER: 1; XY: (-5150,2650)

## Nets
5V0_AO: C189.1 C190.1 C191.1 C193.1 C195.1 C196.1 C208.1 R5.1 R9.1 R280.1 R394.1 U40.5(VCC) U41.5(VCC) U43.5(VCC) U44.5(VCC) U45.5(VCC) U46.5(VCC) U49.5(VCC) ; also on sheet 7 15
5V0_HDMI_EN: U29.17(P14) ; also on sheet 20
GND: C159.2 C162.2 C189.2 C190.2 C191.2 C192.2 C193.2 C194.2 C195.2 C196.2 C208.2 Q45.2(S) Q47.2(S) Q50.2(S) Q51.2(S) Q52.2(S) Q53.2(S) R4.2 R232.2 R239.2 R249.2 R260.2 U28.12(GND) U29.12(GND) U40.3(GND) U41.3(GND) U43.3(GND) U44.3(GND) U45.3(GND) U46.3(GND) U49.3(GND) ; also on sheet 1 2 3 4 5 6 7 9 10 11 12 15 16 17 18 19 20 21 22 23 24 25 26 30
VDD_1V8: C159.1 Q25.1(G) Q26.1(G) R233.1 R234.1 R246.1 R247.1 R248.1 U28.24(VCC) ; also on sheet 4 5 9 10 12 16 17 18 19 20 22 24 30
VDD_3V3_SYS: C162.1 R240.1 R241.1 R259.1 U29.24(VCC) ; also on sheet 1 2 3 4 5 6 12 17 18 19 23 24 25
VDD_LCD_1V8_EN: U29.14(P11) ; also on sheet 17
VDD_SYS_EN: U28.7(P03) ; also on sheet 16
BRIDGE_EN: U28.18(P15) ; also on sheet 17
BRIDGE_IRQ: U28.20(P17) ; also on sheet 17
CAM2_PWDN: U28.11(P07) ; also on sheet 16
CAM2_RST: U28.13(P10) ; also on sheet 16
CAM_AF_PWDN: U28.16(P13) ; also on sheet 16
CAM_AVDD_CAM_EN: U29.18(P15) ; also on sheet 16
CAM_DVDD_CAM_LV_1V5_EN: TP33.1 U29.16(P13)
CAM_VDD_1V2_EN: U28.15(P12) ; also on sheet 16
CAM_VDD_1V8_EN: U28.14(P11) ; also on sheet 16
CARRIER_PWR_ON: R4.1 U43.1(IN1) ; also on sheet 4 6 15 30
CHG_BD_PRSNT_L: U28.17(P14) ; also on sheet 18
DIS_VDD_1V2_EN: U29.15(P12) ; also on sheet 17
EN_VDD_DISP: U29.7(P03) ; also on sheet 17
EN_VDD_TS_1V8_PMIC: U29.5(P01) ; also on sheet 17
EN_VDD_TS_HV_PMIC: U29.6(P02) ; also on sheet 17
FLASH_INHIBIT: U28.10(P06) ; also on sheet 16
GPIO_EXP0_INT: U29.1(INT*) ; also on sheet 30
GPIO_EXP1_INT: U28.1(INT*) ; also on sheet 30
GPIO_EXP2_A0: R248.2 R249.1 U28.21(A0)
GPIO_EXP2_A1: R232.1 R233.2 U28.2(A1)
GPIO_EXP_A0: R259.2 R260.1 U29.21(A0)
GPIO_EXP_A1: R239.1 R240.2 U29.2(A1)
GPIO_EXP_P07_3V3: TP32.1 U29.11(P07)
GPIO_EXP_P16_3V3: U29.19(P16) ; also on sheet 18
GPIO_EXP_P17_3V3: U29.20(P17) ; also on sheet 18
I2C_GP1_CLK_3V3: Q26.3(D) U29.22(SCL) ; also on sheet 2 3 12 17 18 19 30
I2C_GP1_DAT_3V3: Q25.3(D) U29.23(SDA) ; also on sheet 2 3 12 17 18 19 30
I2C_GP1_SCL_1V8_LVL: Q26.2(S) R247.2 U28.22(SCL)
I2C_GP1_SDA_1V8_LVL: Q25.2(S) R246.2 U28.23(SDA)
LCD_BIAS_EN: U28.8(P04) ; also on sheet 17
M2_E_ALERT_R_L: U29.13(P10) ; also on sheet 24
MDM_EN: U29.9(P05) ; also on sheet 24
MDM_RST_L: U29.10(P06) ; also on sheet 24
MOD_PWR_CFG_ID: Q47.1(G) ; also on sheet 15 30
MOD_PWR_CFG_ID_L: Q47.3(D) R394.2 U40.1(A) U41.2(IN2) U49.1(A) ; also on sheet 15
MOD_PWR_ON_STATE: R278.1 ; also on sheet 15
MOD_PWR_ON_STATE_L: R277.1 U49.2(B) ; also on sheet 15
MOD_PWR_ON_STATE_L_MSK: Q51.1(G) U44.2(IN2) U49.4(Y)
MOD_PWR_ON_STATE_L_MSK_Q: C192.1 Q51.3(D) Q52.1(G) R5.2
MOD_PWR_ON_STATE_L_PULSE: R245.1 U44.4(OUT)
MOD_PWR_ON_STATE_L_PULSE_F: C194.1 Q53.1(G) R245.2
MOD_PWR_ON_STATE_L_PULSE_F_Q: Q53.3(D) R284.2
MOD_PWR_ON_STATE_L_R: R277.2 R281.1 U41.1(IN1)
MOD_PWR_ON_STATE_LMSK__DLY: Q52.3(D) R9.2 U44.1(IN1)
MOD_PWR_ON_STATE_MASKED: Q50.1(G) U41.4(OUT)
MOD_PWR_ON_STATE_OR_VIN_EN: R278.2 R279.2 U46.2(I)
MOD_PWR_ON_STATE_OR_VIN_EN_NOT: R281.2 U46.4(Q*)
MOD_VIN_EN: R279.1 ; also on sheet 7 15
NVSR_INT: U28.19(P16) ; also on sheet 17
ONOFF_CTLR_PBOUT: R283.1 U45.2(I) ; also on sheet 15
ONOFF_CTLR_PBOUT_INV: U43.2(IN2) U45.4(Q*)
ONOFF_CTLR_PBOUT_MASKED1: R280.2 R282.1 U43.4(OUT*)
ONOFF_CTLR_PBOUT_MASKED2: Q45.1(G) U40.4(Y*)
ONOFF_CTLR_PBOUT_MASKED_OR_PBOUT: R282.2 R283.2 U40.2(B)
POWER_ON: Q45.3(D) Q50.3(D) R284.1 ; also on sheet 30
PS_VDD_FAN_DISABLE: U29.8(P04) ; also on sheet 12
TCA9539_2_RST_L: R234.2 U28.3(RST*)
TCA9539_RST_L: R241.2 U29.3(RST*)
TORCH_EN: U28.9(P05) ; also on sheet 16
TYPEC_INT: U28.6(P02) ; also on sheet 18
U60_P00: TP502.1 U28.4(P00)
U60_P01: TP501.1 U28.5(P01)
W_DISABLE1_L: U29.4(P00) ; also on sheet 24

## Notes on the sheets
sheet 13
- A
- B
- C
- D
- E
- F
- G
- H
- GPIO EXPANDERS
- 1
- 1
- 2
- 2
- TEGRA GEN2 I2C BUS
- 7'h77
- 3
- 3
- 4
- 4
- TEGRA GEN2 I2C BUS
- 7'h74
- 5
- 5
- NVIDIA CORPORATION
- 2701 SAN TOMAS EXPRESSWAY
- ASSEMBLY
- <ASSEMBLY_DESCRIPTION>
- SANTA CLARA, CA 95050, USA
- PAGE DETAIL
- GPIO Expanders
- NV_PN
- 600-82597-BASE-900
- ALL NVIDIA DESIGN SPECIFICATIONS, REFERENCE SPECIFICATIONS, REFERENCE BOARDS, FILES, DRAWINGS, DIAGNOSTICS, LISTS AND OTHER DOCUMENTS OR INFORMATION (TOGETHER AND SEPARATELY, 'MATERIALS') ARE BEING PROVIDED 'AS IS'. THE MATERIALS MAY
- CONTAIN KNOWN AND UNKNOWN VIOLATIONS OR DEVIATIONS OF INDUSTRY STANDARDS AND SPECIFICATIONS. NVIDIA MAKES NO WARRANTIES, EXPRESSED, IMPLIED, STATUTORY OR OTHERWISE WITH RESPECT TO THE MATERIALS OR OTHERWISE, AND EXPRESSLY DISCLAIMS ALL
- PCB REV
- P2597-C02
- PAGE
- 21 OF 34
- IMPLIED WARRANTIES INCLUDING, WITHOUT LIMITATION, THE WARRANTIES OF DESIGN, OF NONINFRINGEMENT, MERCHANTABILITY OR FITNESS FOR A PARTICULAR PURPOSE, OR ARISING FROM A COURSE OF DEALING, TRADE USAGE, TRADE PRACTICE, OR INDUSTRY STANDARDS.
- BOM REV
- A
- DATE
- 23-OCT-2017
- A
- B
- C
- D
- E
- F
- G
- H
sheet 14
- A
- B
- C
- D
- E
- F
- G
- H
- 1
- 1
- ON OFF STATE
- 2
- 2
- 3
- 3
- ON/OFF MOMENTARY ALL OTHER PULSES
- 4
- 4
- ON/OFF MOMENTARY INITIAL POWER ON PULSE
- 5
- 5
- NVIDIA CORPORATION
- 2701 SAN TOMAS EXPRESSWAY
- ASSEMBLY
- <ASSEMBLY_DESCRIPTION>
- SANTA CLARA, CA 95050, USA
- PAGE DETAIL
- ON OFF CONTROL OUTPUT LOGIC
- NV_PN
- 600-82597-BASE-900
- ALL NVIDIA DESIGN SPECIFICATIONS, REFERENCE SPECIFICATIONS, REFERENCE BOARDS, FILES, DRAWINGS, DIAGNOSTICS, LISTS AND OTHER DOCUMENTS OR INFORMATION (TOGETHER AND SEPARATELY, 'MATERIALS') ARE BEING PROVIDED 'AS IS'. THE MATERIALS MAY
- CONTAIN KNOWN AND UNKNOWN VIOLATIONS OR DEVIATIONS OF INDUSTRY STANDARDS AND SPECIFICATIONS. NVIDIA MAKES NO WARRANTIES, EXPRESSED, IMPLIED, STATUTORY OR OTHERWISE WITH RESPECT TO THE MATERIALS OR OTHERWISE, AND EXPRESSLY DISCLAIMS ALL
- PCB REV
- P2597-C02
- PAGE
- 20 OF 34
- .
- IMPLIED WARRANTIES INCLUDING, WITHOUT LIMITATION, THE WARRANTIES OF DESIGN, OF NONINFRINGEMENT, MERCHANTABILITY OR FITNESS FOR A PARTICULAR PURPOSE, OR ARISING FROM A COURSE OF DEALING, TRADE USAGE, TRADE PRACTICE, OR INDUSTRY STANDARDS.
- BOM REV
- A
- DATE
- 23-OCT-2017
- A
- B
- C
- D
- E
- F
- G
- H
